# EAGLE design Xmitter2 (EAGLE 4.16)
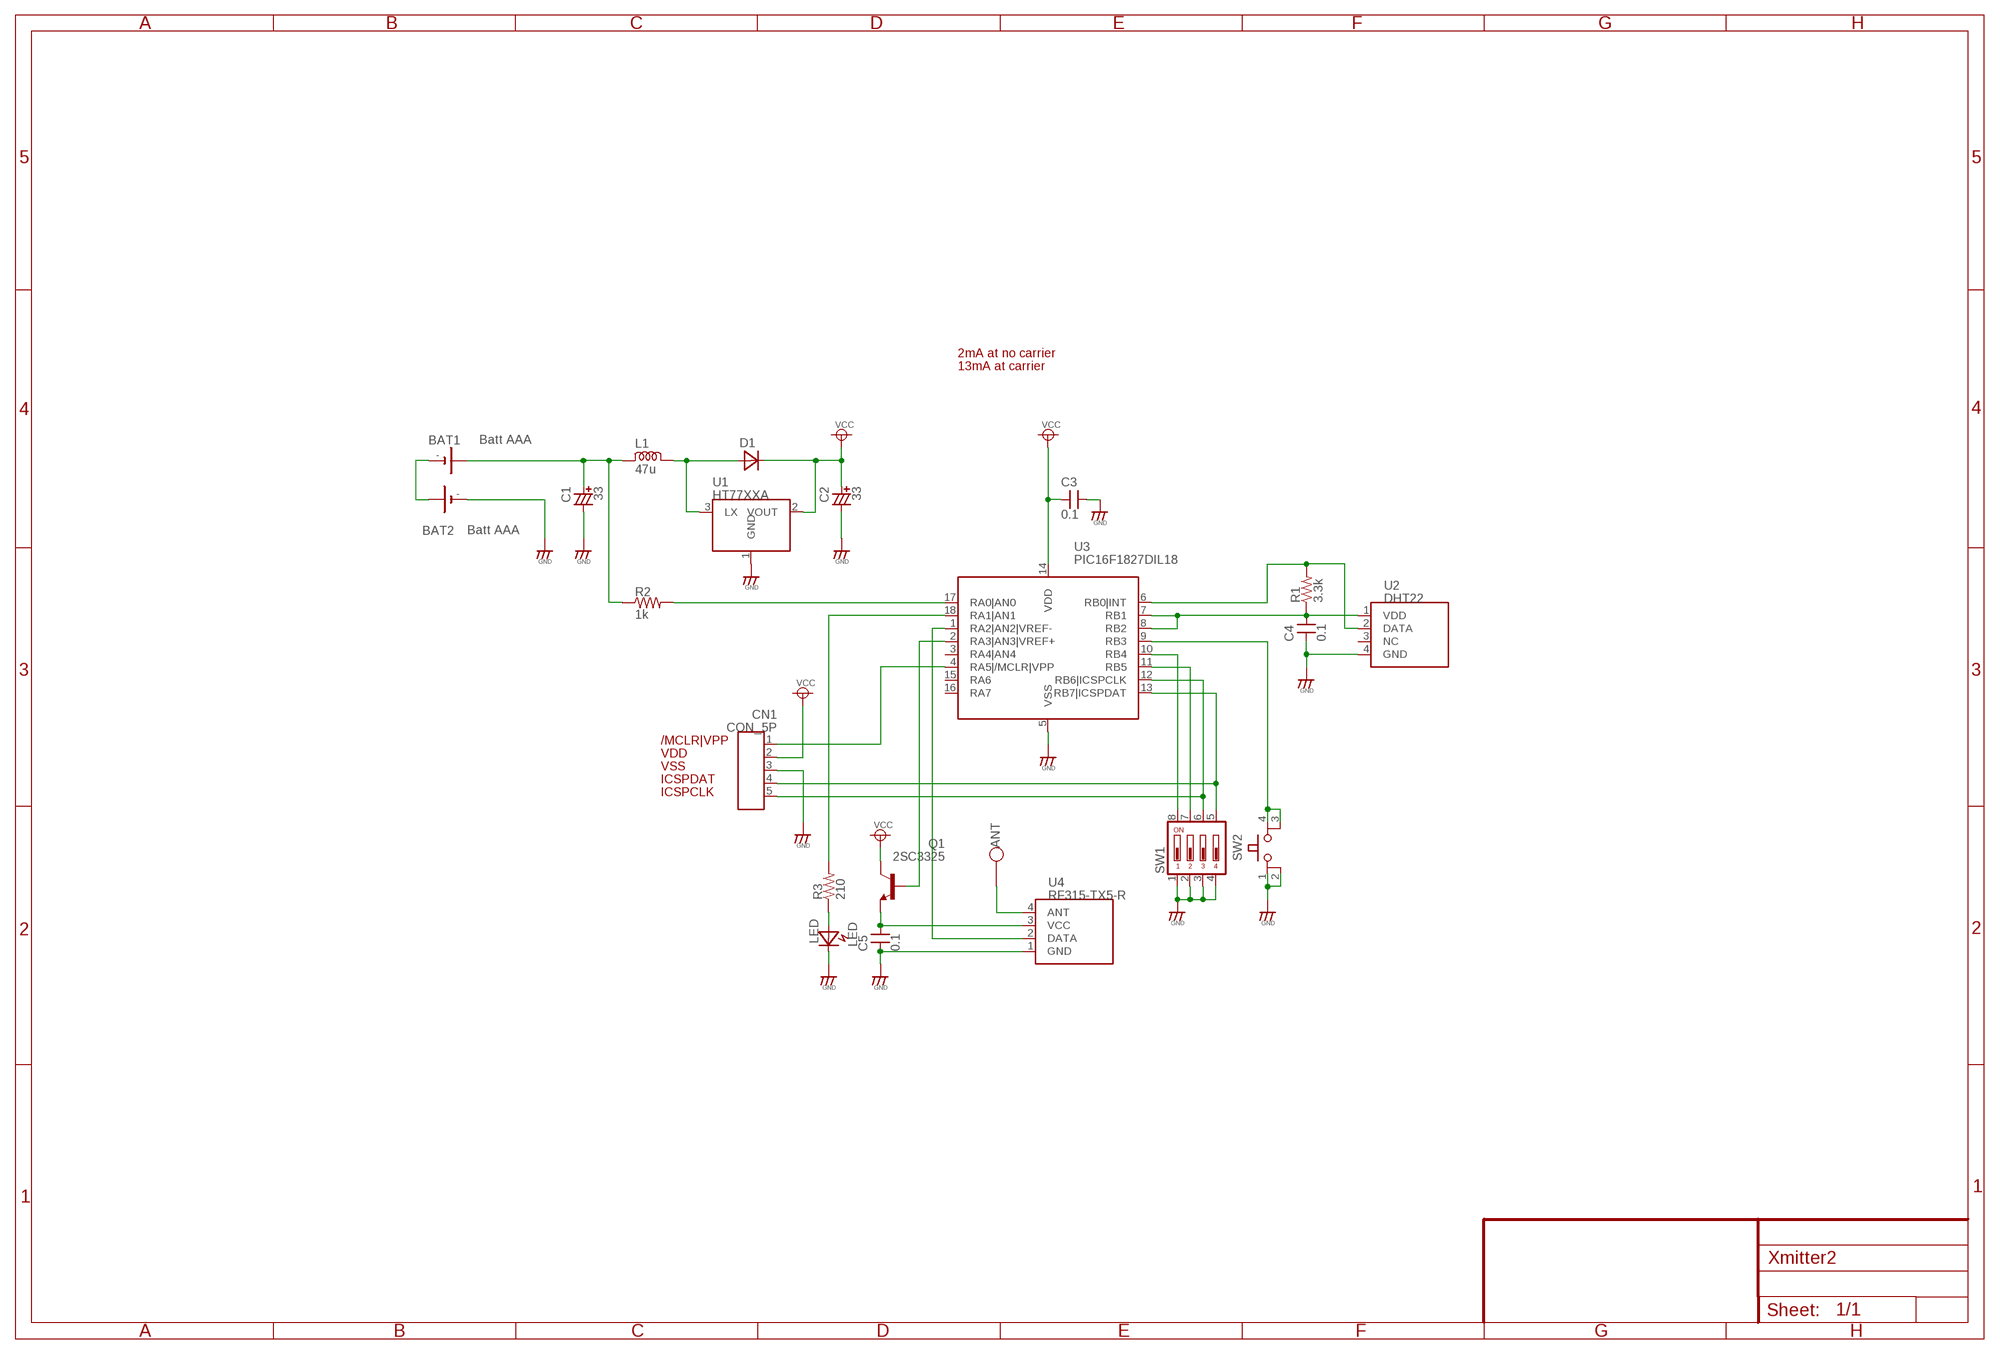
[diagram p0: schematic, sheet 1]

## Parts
ANT  ANT  TP  [TP]
BAT1  Batt AAA  BATT  [BATT_AAA]
BAT2  Batt AAA  BATT  [BATT_AAA]
C1  33  CCAPSMD3528  [CT3528]
C2  33  CCAPSMD3528  [CT3528]
C3  0.1  CAPSM2012  [C2012]
C4  0.1  CAPSM2012  [C2012]
C5  0.1  CAPSM2012  [C2012]
CN1  CON_5P  [CON_HDR_SIP5]
D1  DIODE  [SOD123]
L1  47u  MICRO_INDUCTORVLF4012AT  [VLF4012AT]
LED  LED  [LED_3MM_VIRT_2]
Q1  2SC3325  [SC-59]
R1  3.3k  RSMD2012  [R2012]
R2  1k  RSMD2012  [R2012]
R3  210  RSMD2012  [R2012]
SW1  SD4-04  [SD4-04]
SW2  PUSHSW-6MM  [PUSHSW-6MM]
U1  HT77XXA  [TO92]
U2  DHT22  DHT22HORIZ  [DHT22-HORIZ]
U3  PIC16F1827DIL18  [DIL18]
U4  RF315-TX5-R  [RF315-TX5-R]

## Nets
B+: BAT1.+ C1.+ L1.1 R2.1
DVCC: C2.+ C3.1 CN1.2 D1.K Q1.C U1.2(VOUT) U3.14(VDD) ; supply symbol labelled VCC
GND: BAT2.- C1.- C2.- C3.2 C4.1 C5.1 CN1.3 LED.K SW1.1 SW1.2 SW1.3 SW1.4 SW2.1 SW2.2 U2.4(GND) U3.5(VSS) U4.1(GND)
N$1: D1.A L1.2 U1.3(LX)
N$2: BAT1.- BAT2.+
N$3: CN1.4 SW1.5 U3.13(RB7|ICSPDAT)
N$4: R3.2 U3.18(RA1|AN1)
N$5: R2.2 U3.17(RA0|AN0)
N$6: Q1.B U3.2(RA3|AN3|VREF+)
N$7: CN1.5 SW1.6 U3.12(RB6|ICSPCLK)
N$8: SW1.7 U3.11(RB5)
N$9: SW1.8 U3.10(RB4)
N$10: SW2.3 SW2.4 U3.9(RB3)
N$11: LED.A R3.1
N$12: U3.1(RA2|AN2|VREF-) U4.2(DATA)
N$13: C4.2 R1.1 U2.1(VDD) U3.7(RB1) U3.8(RB2)
N$14: ANT.TP U4.4(ANT)
N$18: CN1.1 U3.4(RA5|/MCLR|VPP)
N$19: C5.2 Q1.E U4.3(VCC)
N$21: R1.2 U2.2(DATA) U3.6(RB0|INT)
Unconnected: U2.3(NC) U3.3(RA4|AN4) U3.15(RA6) U3.16(RA7)

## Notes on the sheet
- 2mA at no carrier
- 13mA at carrier
- /MCLR|VPP
- VDD
- VSS
- ICSPDAT
- ICSPCLK

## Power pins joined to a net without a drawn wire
GND: U1.1(GND)

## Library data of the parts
ANT = WirelessTemp:TP
BAT1 BAT2 = WirelessTemp:BATT
C1 C2 = WirelessTemp:CCAP: Polar capacitor
C3-C5 = WirelessTemp:CAP: Non polar capacitor
CN1 = WirelessTemp:CON_5P
D1 = WirelessTemp:DIODE
L1 = WirelessTemp:MICRO_INDUCTOR
LED = WirelessTemp:LED
Q1 = WirelessTemp:2SC3325
R1-R3 = WirelessTemp:R
SW1 = WirelessTemp:SD4-04: DIL/CODE SWITCH
SW2 = WirelessTemp:PUSHSW-6MM
U1 = WirelessTemp:HT77XXA
U2 = WirelessTemp:DHT22
U3 = WirelessTemp:PIC16F1827: PIC MICRO (16 I/O 10bit-5ch ADC 20MHz)
U4 = WirelessTemp:RF315-TX5-R

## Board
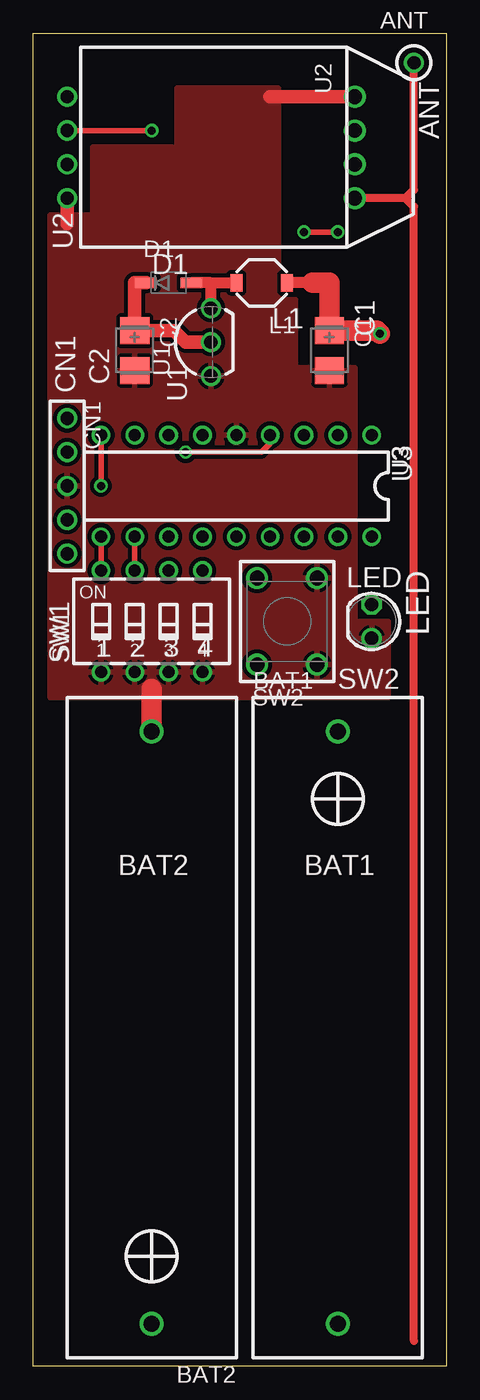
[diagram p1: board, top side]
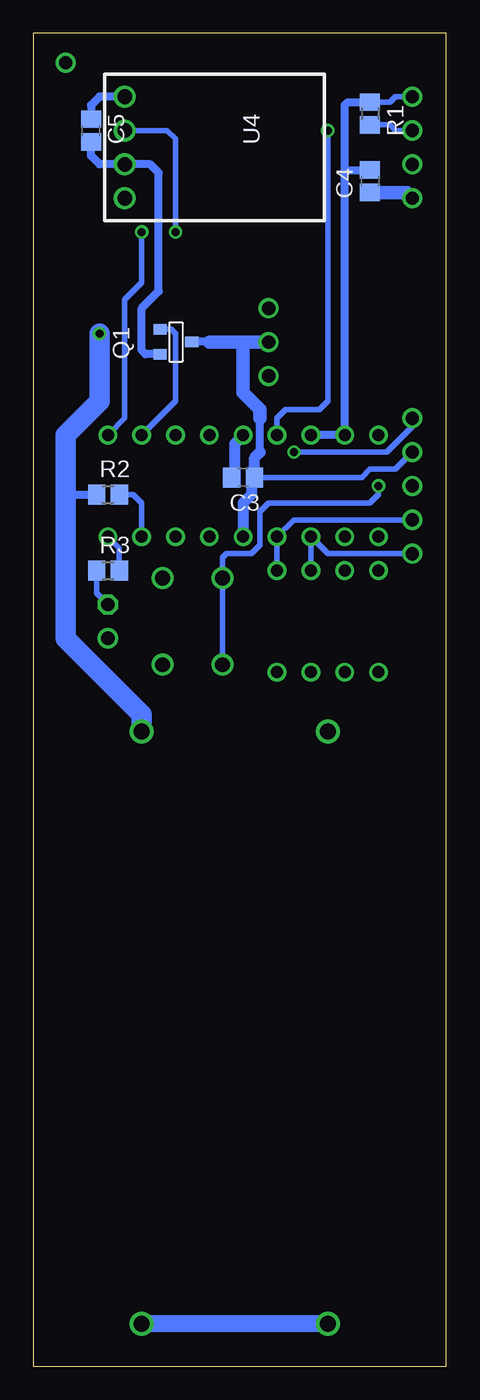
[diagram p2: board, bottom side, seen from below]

Size 31 x 100 mm. Coordinates in mm from the lower left corner, seen from the top.
Outline: 0,0 0,100 31,100 31,0 0,0
Copper layers (1*16): Top 0.035mm / dielectric 1.5mm / Bottom 0.035mm
Design rules "Olimex10mils": minimum track width 10mil, minimum drill 0.6mm, track to track 10mil, track to pad 10mil, pad to pad 10mil, via to via 10mil, smd to smd 10mil, copper to edge 40mil, drill to drill 10mil, minimum pad ring 10mil, minimum via ring 8mil, stop-mask expansion 0mil, vias tented up to drill 0mil, thermal gap 10mil

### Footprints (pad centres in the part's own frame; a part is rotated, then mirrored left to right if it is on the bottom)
TP = drill 1 round: TP 0,0
BATT_AAA = drill 1.2 round: + 0,21.59; - 0,-22.86
CT3528 = smd 2 x 2.2: + -1.5,0; - 1.5,0
C2012 = smd 1.3 x 1.5: 1 -0.85,0; 2 0.85,0
CON_HDR_SIP5 = drill 1 round: 1 -5.08,0; 2 -2.54,0; 3 0,0; 4 2.54,0; 5 5.08,0
SOD123 = smd 1.6 x 0.8: A 1.7,0; K -1.7,0
VLF4012AT = smd 0.9 x 1.3: 1 -1.9,0; 2 1.9,0
LED_3MM_VIRT_2 = drill 1 octagon: A -1.27,0 | drill 1 round: K 1.27,0
SC-59 = smd 0.787 x 0.991: B 0.965,1.168; C 0.025,-1.219; E -0.914,1.168
R2012 = smd 1.3 x 1.5: 1 -0.85,0; 2 0.85,0
SD4-04 = drill 0.9 round: 1 -3.81,-3.81; 2 -1.27,-3.81; 3 1.27,-3.81; 4 3.81,-3.81; 5 3.81,3.81; 6 1.27,3.81; 7 -1.27,3.81; 8 -3.81,3.81
PUSHSW-6MM = drill 1.1 round: 1 -2.25,3.25; 2 -2.25,-3.25; 3 2.25,-3.25; 4 2.25,3.25
TO92 = drill 1 round: 1 -2.54,0; 2 0,0; 3 2.54,0
DHT22-HORIZ = drill 1 round: 1 -3.81,0; 2 -1.27,0; 3 1.27,0; 4 3.81,0
DIL18 = drill 0.9 round: 1 -10.16,-3.81; 2 -7.62,-3.81; 3 -5.08,-3.81; 4 -2.54,-3.81; 5 0,-3.81; 6 2.54,-3.81; 7 5.08,-3.81; 8 7.62,-3.81; 9 10.16,-3.81; 10 10.16,3.81; 11 7.62,3.81; 12 5.08,3.81; 13 2.54,3.81; 14 0,3.81; 15 -2.54,3.81; 16 -5.08,3.81; 17 -7.62,3.81; 18 -10.16,3.81
RF315-TX5-R = drill 1.1 round: 1 -3.81,0; 2 -1.27,0; 3 1.27,0; 4 3.81,0

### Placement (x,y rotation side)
ANT  28.57,97.79 0 top
BAT1  22.86,26.04 0 top
BAT2  8.89,24.77 180 top
C1  22.23,76.2 270 top
C2  7.62,76.2 270 top
C3  15.24,66.67 180 bottom
C4  5.71,88.9 90 bottom
C5  26.67,92.71 270 bottom
CN1  2.54,66.04 270 top
D1  10.16,81.28 0 top
L1  17.14,81.28 180 top
LED  25.4,55.88 270 top
Q1  20.32,76.83 90 bottom
R1  5.71,93.98 270 bottom
R2  25.4,65.41 0 bottom
R3  25.4,59.69 0 bottom
SW1  8.89,55.88 0 top
SW2  19.05,55.88 180 top
U1  13.34,76.83 90 top
U2  2.54,91.44 270 top
U3  15.24,66.04 180 top
U4  24.13,91.44 270 bottom

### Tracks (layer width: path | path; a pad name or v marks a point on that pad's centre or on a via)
B+  (via drill 0.6)
  Top 0.813: 20.95,81.28 L1.1
  Top 1.524: 20.95,81.28 22.23,81.28 C1.+ 25.8,77.7 v26.04,77.47
  Bottom 0.61: 28.57,65.41 R2.1
  Bottom 1.524: BAT1.+ 22.86,48.9 28.57,54.61 28.57,65.41 28.57,69.85 26.04,72.39 v26.04,77.47
DVCC
  Top 1.016: U1.2 11.43,76.83 10.56,77.7 C2.+ 7.62,81.28 D1.K
  Bottom 0.406: CN1.2 3.81,67.31 5.71,67.31 6.35,66.67 C3.1 | 17.78,76.83 17.8,76.86
  Bottom 0.61: 13.97,68.58 13.97,71.12 | 17.8,76.86 Q1.C
  Bottom 0.813: U3.14 15.24,64.77 14.61,65.41 14.61,66.46 C3.1 14.39,68.16 13.97,68.58
  Bottom 1.016: 15.24,76.83 U1.2 | 15.24,76.83 17.78,76.83 | 15.24,76.83 15.24,73.03 13.97,71.75 13.97,71.12
GND
  Top 1.016: 2.54,85.72 U2.4 | 17.78,95.25 U4.1
  Top 1.524: BAT2.- 8.89,50.8
  Bottom 0.61: C5.1 26.67,94.61 26.04,95.25 U4.1
  Bottom 0.813: C3.2 15.88,66.89 15.88,69.22 U3.5
  Bottom 1.016: C4.1 2.96,88.05 U2.4
  pour Top (isolate 0.305): 26.67,55.88 26.67,50.16 1.27,50.16 1.27,86.36 4.45,86.36 4.45,91.44 10.79,91.44 10.79,95.89 18.41,95.89 18.41,80.01 19.68,80.01 19.68,74.93 24.13,74.93 24.13,55.88
N$1
  Top 0.813: 13.34,81.28 L1.2 | 13.34,81.28 D1.A | U1.3 13.34,81.28
N$2
  Bottom 1.27: BAT2.+ BAT1.-
N$3
  Bottom 0.406: SW1.5 U3.13 11.43,63.5 CN1.4
N$4
  Bottom 0.406: R3.2 24.55,61.38 U3.18
N$5
  Bottom 0.406: U3.17 22.86,64.77 23.5,65.41 R2.2
N$6
  Bottom 0.406: U3.2 20.32,72.39 20.32,77.47 20.65,77.8 Q1.B
N$7
  Bottom 0.406: SW1.6 U3.12 8.89,60.96 CN1.5
N$8
  Top 0.406: SW1.7 U3.11
N$9
  Top 0.406: SW1.8 U3.10
N$10  (via drill 0.6)
  Top 0.406: v5.08,66.04 U3.9
  Bottom 0.406: v5.08,66.04 5.08,65.41 5.71,64.77 13.34,64.77 13.97,64.14 13.97,61.59 14.61,60.96 16.51,60.96 16.8,60.67 SW2.3 SW2.4
N$11
  Bottom 0.406: R3.1 26.25,58 LED.A
N$12  (via drill 0.6)
  Top 0.406: v22.86,85.09 v20.32,85.09
  Bottom 0.406: U3.1 24.13,71.12 24.13,80.01 22.86,81.28 | 22.86,81.28 23.5,80.64 | 22.86,81.28 v22.86,85.09 | v20.32,85.09 20.32,92.08 20.95,92.71 U4.2
N$13
  Bottom 0.406: R1.1 4.23,94.83 3.81,95.25 U2.1
  Bottom 0.61: U3.7 U3.8 7.62,89.53 7.62,89.75 | 7.62,89.75 7.62,93.98 7.62,94.61 7.41,94.83 R1.1 | 7.62,89.75 C4.2
N$14
  Top 0.61: 27.94,87.63 U4.4 | 27.94,87.63 28.57,87 28.57,1.91 | 27.94,87.63 28.57,88.27 ANT.TP
N$18  (via drill 0.6)
  Top 0.406: v11.43,68.58 17.14,68.58 17.78,69.22 U3.4
  Bottom 0.406: CN1.1 2.54,70.48 4.45,68.58 v11.43,68.58
N$19
  Bottom 0.406: C5.2 26.67,92.08
  Bottom 0.61: Q1.E 22.58,75.92 22.86,76.2 22.86,79.38 21.59,80.64 21.59,89.53 22.23,90.17 U4.3 26.04,90.17 26.67,90.81 C5.2
N$21  (via drill 0.6)
  Top 0.406: v8.89,92.71 U2.2
  Bottom 0.406: U3.6 12.7,71.12 12.06,71.75 9.53,71.75 8.89,72.39 v8.89,92.71 | R1.2 4.23,93.13 3.81,92.71 U2.2

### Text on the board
Document: Dimension must be corrected to fix deformation
_tPlace: CN1 | 1 | 2 | 3 | 4 | SW2
_tNames: ANT | U2 | D1 | C1 | L1 | C2 | U1 | U3 | LED | SW1 | BAT2 | BAT1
